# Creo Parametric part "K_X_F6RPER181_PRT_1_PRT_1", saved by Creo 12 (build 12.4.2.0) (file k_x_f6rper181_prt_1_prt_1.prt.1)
Units: Custom; MM, KILOGRAM, SECS

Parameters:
  PTC_WM_ITERATION = "0"
  PTC_WM_VERSION = "-.0"
  PTC_WM_LIFECYCLE_STATE = "In Work"
  PTC_WM_LIFECYCLE = "MO_CADDocument"
  PTC_WM_CREATED_BY = "Maximilian Roepper (Z0017RMS: MO)"
  PTC_WM_CREATED_ON = "18-Sep-26 11:36:42 AM"
  PTC_WM_MODIFIED_BY = "Maximilian Roepper (Z0017RMS: MO)"
  PTC_WM_MODIFIED_ON = "18-Sep-26 11:36:46 AM"
  PDMLINKNUMBER = "PDM000071455308"
  PTC_WM_NAME = "k_x_f6rper181_prt_1_prt_1.prt"
  PTC_WM_NUMBER = "PDM000071455308"

Other parameters: WEIGHT, WEIGHT_FACTOR, WEIGHT_ADD, _MASS_TEMP, _DIFF_TEMP, MC_ERRORS, SUPPLIER

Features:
  1. coordinate system
  2. datum plane "PRT_YZ"
  3. datum plane "PRT_XY"
  4. datum plane "PRT_XZ"
  5. coordinate system
  6. datum axis
  7. datum axis
  8. datum axis
  9. coordinate system
  10. imported feature
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
Other named items: PRT, SIEMENS_MO, DRW_VIEW_ORG, PRT_X, PRT_Y, PRT_Z, CS0, ROUGH_GROB

Layers: 00_STD_CSYS-KSYS, 01_STD_PLANES-EBENEN, 02_STD_AXES-ACHSEN, 03_STD_CSYS-KSYS, 24_IMPORT_FEAT-IMPORT_KE

Surfaces: 27 tabulated cylinder, 3 plane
